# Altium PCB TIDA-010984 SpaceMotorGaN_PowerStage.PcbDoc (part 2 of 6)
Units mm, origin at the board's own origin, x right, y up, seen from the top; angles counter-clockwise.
Board outline 177.8 x 152.4 mm, 8 copper layers (Top Layer, DC LINK Layer 2, GND Layer 3, 3V3 Layer 4, Layer 5, Layer 6, GND Layer 7, Bottom Layer), stack 1.554 mm thick; 582 components, 280 nets, 1847 pads, 979 vias.
Unrouted connection lines stored in the file: 474.
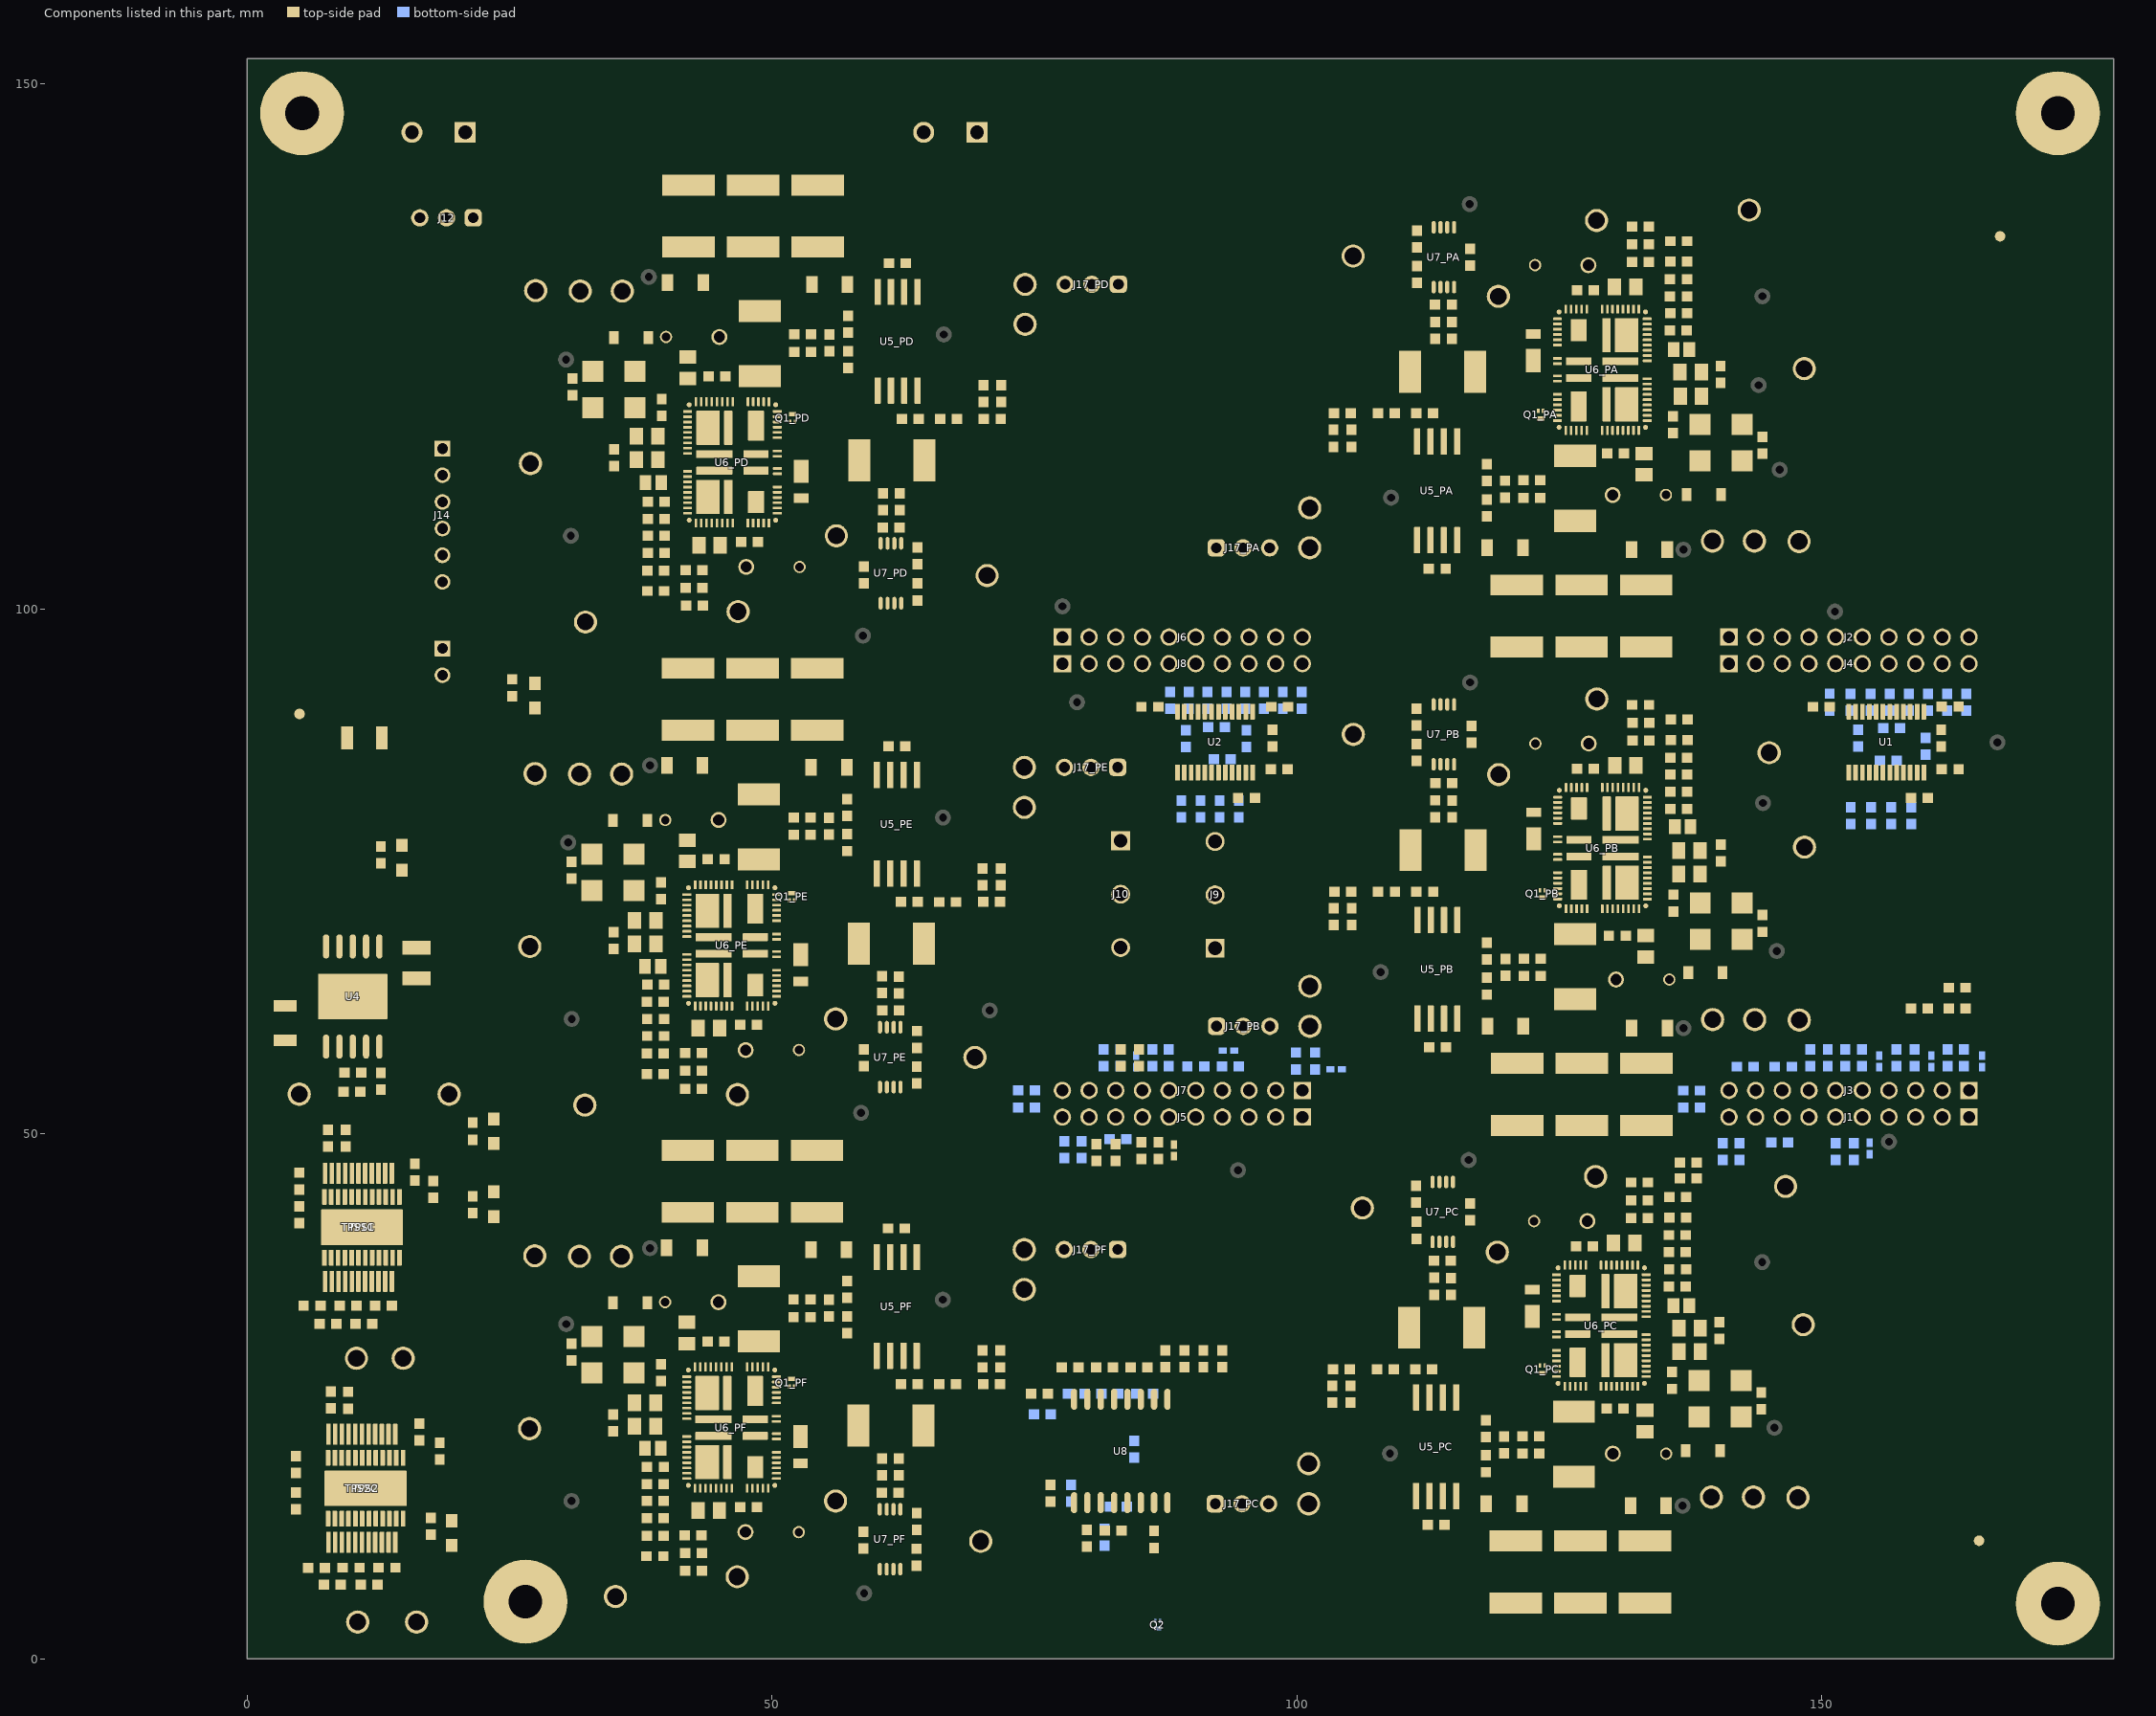
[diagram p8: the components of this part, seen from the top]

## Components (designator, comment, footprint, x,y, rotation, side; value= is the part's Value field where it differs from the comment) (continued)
R80_PC "RC0603FR-072R1L" 0603 144.25,24.547 r90 top locked value=2.10 (schematic designator R80)
R80_PD "RC0603FR-072R1L" 0603 31,121.141 r270 top locked value=2.10 (schematic designator R80)
R80_PE "RC0603FR-072R1L" 0603 30.932,75.129 r270 top locked value=2.10 (schematic designator R80)
R80_PF "RC0603FR-072R1L" 0603 30.918,29.205 r270 top value=2.10 (schematic designator R80)
R81_PA "RC0603FR-0710KL" 0603 132.758,133.046 r180 top value=10.0k (schematic designator R81)
R81_PB "RC0603FR-0710KL" 0603 132.78,87.477 r180 top value=10.0k (schematic designator R81)
R81_PC "RC0603FR-0710KL" 0603 132.66,41.99 r180 top locked value=10.0k (schematic designator R81)
R81_PD "RC0603FR-0710KL" 0603 42.59,103.698 r0 top locked value=10.0k (schematic designator R81)
R81_PE "RC0603FR-0710KL" 0603 42.522,57.686 r0 top locked value=10.0k (schematic designator R81)
R81_PF "RC0603FR-0710KL" 0603 42.508,11.762 r0 top value=10.0k (schematic designator R81)
R82_PA "CRCW060320R0FKEA" 0603 136.373,128.156 r0 top value=20.0 (schematic designator R82)
R82_PB "CRCW060320R0FKEA" 0603 136.395,82.587 r0 top value=20.0 (schematic designator R82)
R82_PC "CRCW060320R0FKEA" 0603 136.275,37.1 r0 top locked value=20.0 (schematic designator R82)
R82_PD "CRCW060320R0FKEA" 0603 38.975,108.588 r180 top locked value=20.0 (schematic designator R82)
R82_PE "CRCW060320R0FKEA" 0603 38.907,62.576 r180 top locked value=20.0 (schematic designator R82)
R82_PF "CRCW060320R0FKEA" 0603 38.893,16.652 r180 top value=20.0 (schematic designator R82)
R83_PA "CRCW060320R0FKEA" 0603 136.364,129.784 r0 top value=20.0 (schematic designator R83)
R83_PB "CRCW060320R0FKEA" 0603 136.386,84.215 r0 top value=20.0 (schematic designator R83)
R83_PC "CRCW060320R0FKEA" 0603 136.266,38.728 r0 top locked value=20.0 (schematic designator R83)
R83_PD "CRCW060320R0FKEA" 0603 38.984,106.96 r180 top locked value=20.0 (schematic designator R83)
R83_PE "CRCW060320R0FKEA" 0603 38.916,60.948 r180 top locked value=20.0 (schematic designator R83)
R83_PF "CRCW060320R0FKEA" 0603 38.902,15.024 r180 top value=20.0 (schematic designator R83)
R84_PA "RC0603JR-070RL" 0603 132.737,136.43 r0 top value=0 (schematic designator R84)
R84_PB "RC0603JR-070RL" 0603 132.759,90.861 r0 top value=0 (schematic designator R84)
R84_PC "RC0603JR-070RL" 0603 132.639,45.374 r0 top locked value=0 (schematic designator R84)
R84_PD "RC0603JR-070RL" 0603 42.611,100.314 r180 top locked value=0 (schematic designator R84)
R84_PE "RC0603JR-070RL" 0603 42.543,54.302 r180 top locked value=0 (schematic designator R84)
R84_PF "RC0603JR-070RL" 0603 42.529,8.378 r180 top value=0 (schematic designator R84)
R85_PA "CRE2512-FZ-R005E-3" CRE2512-R5_R9 113.912,122.598 r180 top locked value=0.005 (schematic designator R85)
R85_PB "CRE2512-FZ-R005E-3" CRE2512-R5_R9 113.934,77.029 r180 top value=0.005 (schematic designator R85)
R85_PC "CRE2512-FZ-R005E-3" CRE2512-R5_R9 113.814,31.542 r180 top locked value=0.005 (schematic designator R85)
R85_PD "CRE2512-FZ-R005E-3" CRE2512-R5_R9 61.436,114.146 r0 top locked value=0.005 (schematic designator R85)
R85_PE "CRE2512-FZ-R005E-3" CRE2512-R5_R9 61.368,68.134 r0 top locked value=0.005 (schematic designator R85)
R85_PF "CRE2512-FZ-R005E-3" CRE2512-R5_R9 61.354,22.21 r0 top value=0.005 (schematic designator R85)
R86_PA "RC0603FR-0757K6L" 0603 136.4,135.031 r0 top value=57.6k (schematic designator R86)
R86_PB "RC0603FR-0757K6L" 0603 136.423,89.462 r0 top value=57.6k (schematic designator R86)
R86_PC "RC0603FR-0757K6L" 0603 136.302,43.975 r0 top locked value=57.6k (schematic designator R86)
R86_PD "RC0603FR-0757K6L" 0603 38.948,101.713 r180 top locked value=57.6k (schematic designator R86)
R86_PE "RC0603FR-0757K6L" 0603 38.879,55.701 r180 top locked value=57.6k (schematic designator R86)
R86_PF "RC0603FR-0757K6L" 0603 38.865,9.777 r180 top value=57.6k (schematic designator R86)
R87_PA "RC0603JR-070RL" 0603 132.749,134.734 r0 top value=0 (schematic designator R87)
R87_PB "RC0603JR-070RL" 0603 132.771,89.165 r0 top value=0 (schematic designator R87)
R87_PC "RC0603JR-070RL" 0603 132.651,43.678 r0 top locked value=0 (schematic designator R87)
R87_PD "RC0603JR-070RL" 0603 42.599,102.01 r180 top locked value=0 (schematic designator R87)
R87_PE "RC0603JR-070RL" 0603 42.531,55.998 r180 top locked value=0 (schematic designator R87)
R87_PF "RC0603JR-070RL" 0603 42.517,10.074 r180 top value=0 (schematic designator R87)
R88_PA "RC0603FR-07100KL" 0603 104.348,118.644 r0 top locked value=100k (schematic designator R88)
R88_PB "RC0603FR-07100KL" 0603 104.37,73.075 r0 top locked value=100k (schematic designator R88)
R88_PC "RC0603FR-07100KL" 0603 104.25,27.589 r0 top locked value=100k (schematic designator R88)
R88_PD "RC0603FR-07100KL" 0603 71,118.1 r180 top locked value=100k (schematic designator R88)
R88_PE "RC0603FR-07100KL" 0603 70.932,72.088 r180 top locked value=100k (schematic designator R88)
R88_PF "RC0603FR-07100KL" 0603 70.918,26.163 r180 top value=100k (schematic designator R88)
R89_PA "RC0603JR-070RL" 0603 114.78,126.525 r90 top locked value=0 (schematic designator R89)
R89_PB "RC0603JR-070RL" 0603 114.802,80.956 r90 top value=0 (schematic designator R89)
R89_PC "RC0603JR-070RL" 0603 114.682,35.469 r90 top locked value=0 (schematic designator R89)
R89_PD "RC0603JR-070RL" 0603 60.568,110.219 r270 top locked value=0 (schematic designator R89)
R89_PE "RC0603JR-070RL" 0603 60.5,64.207 r270 top locked value=0 (schematic designator R89)
R89_PF "RC0603JR-070RL" 0603 60.486,18.282 r270 top value=0 (schematic designator R89)
R90_PA "RC0603JR-070RL" 0603 113.18,126.538 r90 top locked value=0 (schematic designator R90)
R90_PB "RC0603JR-070RL" 0603 113.202,80.969 r90 top value=0 (schematic designator R90)
R90_PC "RC0603JR-070RL" 0603 113.082,35.482 r90 top locked value=0 (schematic designator R90)
R90_PD "RC0603JR-070RL" 0603 62.168,110.206 r270 top locked value=0 (schematic designator R90)
R90_PE "RC0603JR-070RL" 0603 62.1,64.194 r270 top locked value=0 (schematic designator R90)
R90_PF "RC0603JR-070RL" 0603 62.086,18.269 r270 top value=0 (schematic designator R90)
R91_PA "RC0603FR-0735K7L" 0603 136.395,133.091 r0 top value=35.7k (schematic designator R91)
R91_PB "RC0603FR-0735K7L" 0603 136.417,87.522 r0 top value=35.7k (schematic designator R91)
R91_PC "RC0603FR-0735K7L" 0603 136.297,42.035 r0 top locked value=35.7k (schematic designator R91)
R91_PD "RC0603FR-0735K7L" 0603 38.953,103.653 r180 top locked value=35.7k (schematic designator R91)
R91_PE "RC0603FR-0735K7L" 0603 38.885,57.641 r180 top locked value=35.7k (schematic designator R91)
R91_PF "RC0603FR-0735K7L" 0603 38.871,11.717 r180 top value=35.7k (schematic designator R91)
R92_PA "RC0603FR-074K22L" 0603 105.207,116.25 r90 top locked value=4.22k (schematic designator R92)
R92_PB "RC0603FR-074K22L" 0603 105.229,70.681 r90 top locked value=4.22k (schematic designator R92)
R92_PC "RC0603FR-074K22L" 0603 105.109,25.194 r90 top locked value=4.22k (schematic designator R92)
R92_PD "RC0603FR-074K22L" 0603 70.141,120.494 r270 top locked value=4.22k (schematic designator R92)
R92_PE "RC0603FR-074K22L" 0603 70.073,74.482 r270 top locked value=4.22k (schematic designator R92)
R92_PF "RC0603FR-074K22L" 0603 70.059,28.558 r270 top value=4.22k (schematic designator R92)
R93_ "RC0603FR-0710KL" 0603 130.531,68.873 r0 top value=10.0k (schematic designator R93)
R93_ "RC0603FR-0710KL" 0603 44.684,30.221 r180 top value=10.0k (schematic designator R93)
R93_ "RC0603FR-0710KL" 0603 44.698,76.145 r180 top value=10.0k (schematic designator R93)
R93_ "RC0603FR-0710KL" 0603 44.766,122.157 r180 top value=10.0k (schematic designator R93)
R93_ "RC0603FR-0710KL" 0603 130.307,23.848 r0 top locked value=10.0k (schematic designator R93)
R93_ "RC0603FR-0710KL" 0603 130.358,114.806 r0 top value=10.0k (schematic designator R93)
R94_PA "RC0603JR-070RL" 0603 111.469,135.25 r270 top value=0 (schematic designator R94)
R94_PB "RC0603JR-070RL" 0603 111.403,89.695 r270 top value=0 (schematic designator R94)
R94_PC "RC0603JR-070RL" 0603 111.371,44.25 r270 top value=0 (schematic designator R94)
R94_PD "RC0603JR-070RL" 0603 63.879,101.619 r90 top value=0 (schematic designator R94)
R94_PE "RC0603JR-070RL" 0603 63.797,55.607 r90 top value=0 (schematic designator R94)
R94_PF "RC0603JR-070RL" 0603 63.783,9.682 r90 top value=0 (schematic designator R94)
R95_PA "RC0603FR-0710KL" 0603 127.487,130.35 r0 top value=10.0k (schematic designator R95)
R95_PB "RC0603FR-0710KL" 0603 127.509,84.781 r0 top value=10.0k (schematic designator R95)
R95_PC "RC0603FR-0710KL" 0603 127.389,39.294 r0 top locked value=10.0k (schematic designator R95)
R95_PD "RC0603FR-0710KL" 0603 47.861,106.394 r180 top locked value=10.0k (schematic designator R95)
R95_PE "RC0603FR-0710KL" 0603 47.793,60.382 r180 top locked value=10.0k (schematic designator R95)
R95_PF "RC0603FR-0710KL" 0603 47.779,14.458 r180 top value=10.0k (schematic designator R95)
R96 "RC0603FR-0710KL" 0603 87.471,28.581 r90 top value=10.0k
R97 "RC0603FR-0710KL" 0603 89.285,28.581 r90 top value=10.0k
R98 "RC0603FR-0710KL" 0603 92.913,28.581 r90 top value=10.0k
R99 "RC0603FR-0710KL" 0603 91.099,28.581 r90 top value=10.0k
R100 "RC0603JR-070RL" 0603 86.408,11.371 r270 top value=0
R101 "RC0603JR-070RL" 0603 84.957,27.75 r180 top value=0
R102 "CRCW060313K3FKEA" 0603 12.75,76.569 r90 top value=13.3k
R103 "RC0603JR-070RL" 0603 82.5,12.221 r180 top value=0
R104 "RC0603JR-070RL" 0603 81.707,27.75 r180 top value=0
R105 "RC0603JR-070RL" 0603 76.55,15.75 r270 top value=0
R106 "RC0603JR-070RL" 0603 75.5,25.25 r0 top value=0
R107 "RC0603JR-070RL" 0603 80,11.5 r270 top value=0
R108 "RC0603JR-070RL" 0603 78.412,27.75 r0 top value=0
R109 "RC0603FR-0720RL" 0603 74.25,54.142 r0 bottom value=20.0
R110 "CRCW060313K3FKEA" 0603 25.25,92.5 r90 top locked value=13.3k
R111 "RC0603FR-076K65L" 0603 21.5,43.25 r90 top value=6.65k
R112 "RC0603FR-074K22L" 0603 17.5,12.64 r90 top value=4.22k
R113 "RC0603FR-0720RL" 0603 82.95,49.5 r0 bottom value=20.0
R114 "RC0603FR-072K1L" 0603 21.5,50.25 r90 top value=2.10k
R115 "RC0603JR-070RL" 0603 137.307,45.75 r0 top value=0
R116 "RC0603JR-070RL" 0603 137.296,47.25 r0 top value=0
R117 "RC0603JR-070RL" 0603 80.907,48.22 r90 top value=0
R118 "RC0603JR-070RL" 0603 82.756,48.22 r90 top value=0
TP1 "5010" Keystone5010 14.875,28.624 r0 top locked
TP2 "5012" Keystone5012 10.423,28.624 r0 top locked
TP3 "5010" Keystone5010 16.153,3.5 r0 top locked
TP4 "5012" Keystone5012 10.549,3.5 r0 top locked
TP5 "5010" Keystone5010 4.973,53.784 r0 top locked
TP6_PA "5129" Keystone5129 101.228,105.821 r180 top locked (schematic designator TP6)
TP6_PB "5129" Keystone5129 101.25,60.252 r180 top locked (schematic designator TP6)
TP6_PC "5129" Keystone5129 101.13,14.766 r180 top locked (schematic designator TP6)
TP6_PD "5129" Keystone5129 74.12,130.923 r0 top locked (schematic designator TP6)
TP6_PE "5129" Keystone5129 74.052,84.911 r0 top locked (schematic designator TP6)
TP6_PF "5129" Keystone5129 74.038,38.986 r0 top (schematic designator TP6)
TP7_PA "5010" Keystone5010 148.348,122.887 r180 top locked (schematic designator TP7)
TP7_PB "5010" Keystone5010 148.37,77.318 r180 top (schematic designator TP7)
TP7_PC "5010" Keystone5010 148.25,31.831 r180 top locked (schematic designator TP7)
TP7_PD "5010" Keystone5010 27,113.857 r0 top locked (schematic designator TP7)
TP7_PE "5010" Keystone5010 26.932,67.845 r0 top locked (schematic designator TP7)
TP7_PF "5010" Keystone5010 26.918,21.921 r0 top (schematic designator TP7)
TP8_PA "5010" Keystone5010 143.598,106.46 r180 top locked (schematic designator TP8)
TP8_PB "5010" Keystone5010 143.62,60.891 r180 top (schematic designator TP8)
TP8_PC "5010" Keystone5010 143.5,15.404 r180 top locked (schematic designator TP8)
TP8_PD "5010" Keystone5010 31.75,130.284 r0 top locked (schematic designator TP8)
TP8_PE "5010" Keystone5010 31.682,84.272 r0 top locked (schematic designator TP8)
TP8_PF "5010" Keystone5010 31.668,38.348 r0 top (schematic designator TP8)
TP9_PA "5010" Keystone5010 128.565,136.994 r180 top locked (schematic designator TP9)
TP9_PB "5010" Keystone5010 128.587,91.425 r180 top (schematic designator TP9)
TP9_PC "5010" Keystone5010 128.467,45.938 r180 top locked (schematic designator TP9)
TP9_PD "5010" Keystone5010 46.783,99.75 r0 top locked (schematic designator TP9)
TP9_PE "5010" Keystone5010 46.715,53.738 r0 top locked (schematic designator TP9)
TP9_PF "5010" Keystone5010 46.701,7.814 r0 top (schematic designator TP9)
TP10 "5010" Keystone5010 19.25,53.784 r0 top locked
TP10_PA "5013" Keystone5013 119.206,129.784 r270 top locked (schematic designator TP10)
TP10_PB "5013" Keystone5013 119.229,84.215 r270 top (schematic designator TP10)
TP10_PC "5013" Keystone5013 119.109,38.728 r270 top locked (schematic designator TP10)
TP10_PD "5013" Keystone5013 56.141,106.96 r90 top locked (schematic designator TP10)
TP10_PE "5013" Keystone5013 56.073,60.948 r90 top locked (schematic designator TP10)
TP10_PF "5013" Keystone5013 56.059,15.024 r90 top (schematic designator TP10)
TP11_PA "5010" Keystone5010 139.598,106.46 r180 top locked (schematic designator TP11)
TP11_PB "5010" Keystone5010 139.62,60.891 r180 top (schematic designator TP11)
TP11_PC "5010" Keystone5010 139.5,15.404 r180 top locked (schematic designator TP11)
TP11_PD "5010" Keystone5010 35.75,130.284 r0 top locked (schematic designator TP11)
TP11_PE "5010" Keystone5010 35.682,84.272 r0 top locked (schematic designator TP11)
TP11_PF "5010" Keystone5010 35.668,38.348 r0 top (schematic designator TP11)
TP12_PA "5129" Keystone5129 101.228,109.631 r270 top locked (schematic designator TP12)
TP12_PB "5129" Keystone5129 101.25,64.062 r270 top locked (schematic designator TP12)
TP12_PC "5129" Keystone5129 101.13,18.576 r270 top locked (schematic designator TP12)
TP12_PD "5129" Keystone5129 74.12,127.113 r90 top locked (schematic designator TP12)
TP12_PE "5129" Keystone5129 74.052,81.101 r90 top locked (schematic designator TP12)
TP12_PF "5129" Keystone5129 74.038,35.176 r90 top (schematic designator TP12)
TP13_PA "HS_Gate" TESTPOINT_PIGTAIL 130.083,110.855 r90 top (schematic designator TP13)
TP13_PB "HS_Gate" TESTPOINT_PIGTAIL 130.406,64.7 r90 top (schematic designator TP13)
TP13_PC "HS_Gate" TESTPOINT_PIGTAIL 130.113,19.538 r90 top (schematic designator TP13)
TP13_PD "HS_Gate" TESTPOINT_PIGTAIL 44.992,125.907 r270 top (schematic designator TP13)
TP13_PE "HS_Gate" TESTPOINT_PIGTAIL 44.924,79.895 r270 top (schematic designator TP13)
TP13_PF "HS_Gate" TESTPOINT_PIGTAIL 44.91,33.971 r270 top (schematic designator TP13)
TP14_PA "LS_Gate" TESTPOINT_PIGTAIL 127.786,132.744 r270 top (schematic designator TP14)
TP14_PB "LS_Gate" TESTPOINT_PIGTAIL 127.808,87.175 r270 top (schematic designator TP14)
TP14_PC "LS_Gate" TESTPOINT_PIGTAIL 127.688,41.688 r270 top locked (schematic designator TP14)
TP14_PD "LS_Gate" TESTPOINT_PIGTAIL 47.562,104 r90 top locked (schematic designator TP14)
TP14_PE "LS_Gate" TESTPOINT_PIGTAIL 47.494,57.988 r90 top locked (schematic designator TP14)
TP14_PF "LS_Gate" TESTPOINT_PIGTAIL 47.48,12.064 r90 top (schematic designator TP14)
TP16_PA "5011" Keystone5011 147.848,106.413 r270 top locked (schematic designator TP16)
TP16_PB "5011" Keystone5011 147.87,60.844 r270 top (schematic designator TP16)
TP16_PC "5011" Keystone5011 147.75,15.357 r270 top locked (schematic designator TP16)
TP16_PD "5011" Keystone5011 27.5,130.331 r90 top locked (schematic designator TP16)
TP16_PE "5011" Keystone5011 27.432,84.319 r90 top locked (schematic designator TP16)
TP16_PF "5011" Keystone5011 27.418,38.395 r90 top (schematic designator TP16)
TP17_PA "5011" Keystone5011 143.098,137.994 r270 top locked (schematic designator TP17)
TP17_PB "5011" Keystone5011 145,86.303 r270 top (schematic designator TP17)
TP17_PC "5011" Keystone5011 146.57,45 r270 top locked (schematic designator TP17)
TP17_PD "5011" Keystone5011 32.25,98.75 r90 top locked (schematic designator TP17)
TP17_PE "5011" Keystone5011 32.182,52.738 r90 top (schematic designator TP17)
TP17_PF "5011" Keystone5011 35.091,5.931 r90 top (schematic designator TP17)
TP18_PA "5011" Keystone5011 105.366,133.618 r270 top locked (schematic designator TP18)
TP18_PB "5011" Keystone5011 105.389,88.049 r270 top locked (schematic designator TP18)
TP18_PC "5011" Keystone5011 106.25,42.949 r270 top (schematic designator TP18)
TP18_PD "5011" Keystone5011 70.5,103.173 r90 top (schematic designator TP18)
TP18_PE "5011" Keystone5011 69.343,57.276 r90 top (schematic designator TP18)
TP18_PF "5011" Keystone5011 69.9,11.189 r90 top (schematic designator TP18)
TPS1 "TPS7H1121MPWPTSEP" PWP0024R-MFG 10.943,41.098 r270 top
TPS1C "TPS7H1121HFT/EM" HFT0022A-C01-MFG 10.618,41.098 r270 top
TPS2 "TPS7H1121MPWPTSEP" PWP0024R-MFG 11.292,16.24 r270 top locked
TPS2C "TPS7H1121HFT/EM" HFT0022A-C01-MFG 10.943,16.24 r270 top locked
U1 "SN54SLC8T245PWTSEP" PW0024A-MFG 156.166,87.316 r270 top locked
U2 "SN54SLC8T245PWTSEP" PW0024A-MFG 92.216,87.316 r270 top locked
U4 "TPS7A4501HKU/EM" HKU0010A-IPC_B 10.069,63.081 r270 top
U5_PA "INA901HKX/EM" HKX0008A_Custom_A 113.374,111.246 r270 top locked (schematic designator U5)
U5_PB "INA901HKX/EM" HKX0008A_Custom_A 113.396,65.677 r270 top (schematic designator U5)
U5_PC "INA901HKX/EM" HKX0008A_Custom_A 113.276,20.19 r270 top locked (schematic designator U5)
U5_PD "INA901HKX/EM" HKX0008A_Custom_A 61.974,125.498 r90 top locked (schematic designator U5)
U5_PE "INA901HKX/EM" HKX0008A_Custom_A 61.906,79.486 r90 top locked (schematic designator U5)
U5_PF "INA901HKX/EM" HKX0008A_Custom_A 61.892,33.562 r90 top (schematic designator U5)
U6_PA "TPS7H6101MNPRTSHP" NPR0064A-MFG 129.107,122.785 r180 top (schematic designator U6)
U6_PB "TPS7H6101MNPRTSHP" NPR0064A-MFG 129.129,77.216 r180 top (schematic designator U6)
U6_PC "TPS7H6101MNPRTSHP" NPR0064A-MFG 129.009,31.729 r180 top locked (schematic designator U6)
U6_PD "TPS7H6101MNPRTSHP" NPR0064A-MFG 46.241,113.959 r0 top locked (schematic designator U6)
U6_PE "TPS7H6101MNPRTSHP" NPR0064A-MFG 46.173,67.947 r0 top locked (schematic designator U6)
U6_PF "TPS7H6101MNPRTSHP" NPR0064A-MFG 46.159,22.023 r0 top (schematic designator U6)
U7_PA "INA240A1PWR" PW0008A_L 114.009,133.5 r90 top (schematic designator U7)
U7_PB "INA240A1PWR" PW0008A_L 114.009,88.049 r90 top (schematic designator U7)
U7_PC "INA240A1PWR" PW0008A_L 113.911,42.563 r90 top (schematic designator U7)
U7_PD "INA240A1PWR" PW0008A_L 61.339,103.397 r270 top (schematic designator U7)
U7_PE "INA240A1PWR" PW0008A_L 61.271,57.31 r270 top (schematic designator U7)
U7_PF "INA240A1PWR" PW0008A_L 61.257,11.386 r270 top (schematic designator U7)
U8 "5962R2021401VXC" HKT0016A-IPC_C 83.233,19.798 r90 top
ZZ1 "This Assembly Note is for PCB labels only" AssemblyNoteLabel 3.515,163.673 r0 top
ZZ2 "These assemblies are ESD sensitive, ESD precautions shall be observed." AssemblyNote 4.719,157.75 r0 top
ZZ3 "These assemblies must be clean and free from flux and all contaminants. Use of no clean flux is not acceptable." AssemblyNote 4.519,154.75 r0 top
ZZ4 "These assemblies must comply with workmanship standards IPC-A-610 Class 2, unless otherwise specified." AssemblyNote 3.5,161.5 r0 top

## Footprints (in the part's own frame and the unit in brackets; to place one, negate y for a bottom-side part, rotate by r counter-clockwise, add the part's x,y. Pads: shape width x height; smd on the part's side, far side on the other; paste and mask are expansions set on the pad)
0603 [mm] "0603 from SM-752 data"
  rect 1x0.95 smd: 1(-0.8,0) 2(0.8,0)
  silkscreen extent -1.52,-0.69 1.52,0.69, body extent -0.87,-0.47 0.87,0.47, height 1
0805_HV [mil] "0805 with 30mil clearance between pads"
  rect 50x63 smd: 1(-40,0) 2(40,0)
  silkscreen extent -74,-40 74,40, body extent -43,-29 43,29, height 57
0805L [mm] "0805 from SM-752 data"
  rect 1.1x1.4 smd: 1(-0.75,0) 2(0.75,0)
  body extent -1.1,-0.72 1.1,0.72, height 1.45
1206_180 [mm] "1206_180"
  rect 1.1x1.6 smd: 1(-1.7,0) 2(1.7,0)
  silkscreen extent -0.9,-1 0.9,1, body extent -1.75,-0.95 1.75,0.95, height 1.8
1210_150 [mm] "1210"
  rect 1.3x2.7 smd: 1(-1.45,0) 2(1.45,0)
  silkscreen extent -2.32,-1.57 2.32,1.57, body extent -1.7,-1.35 1.7,1.35, height 1.5
1210_280 [mm] "SMD, 2-Leads, Body 3.6x2.8mm, Height 2.8mm"
  rect 1.1x2.2 smd: 1(-1.65,0) 2(1.65,0)
  silkscreen extent -0.84,-1.4 0.84,1.4, body extent -1.8,-1.4 1.8,1.4, height 2.8
APT2012_Green [mm] "SMD, 2-Leads, Body 2x1.25mm"
  rect 1.25x1.1 smd: 1(-1.175,0) 2(1.175,0)
  silkscreen extent -1.5,-1 2.4,1, body extent -1,-0.62 1,0.63, height 0.76
AssemblyNote [mm] "Assembly Note"
AssemblyNoteLabel [mm] "Assembly Note for PCB Labels"
CE_Mark_5mm [mm] "Minimum text height for CE Mark"
  silkscreen extent -3.5,-2.5 3.5,2.5
CKG57N [mm] "Chip Capacitor, Body 6.0x5.0x5.0mm,"
  rect 2x5 smd: 1(-2.95,0) 2(2.95,0)
  silkscreen extent -3.2,-2.8 3.2,2.8, body extent -3.3,-2.75 3.3,2.75, height 5.5
CONN_PEC02SAAN [mm] "SULLINS"
  rrect7% 1.5x1.5 hole 1.016: 1(-1.27,0)
  round 1.5 hole 1.016: 2(1.27,0)
  silkscreen extent -2.54,-1.52 2.54,1.27, body extent -2.54,-1.27 2.54,1.27, height 8.38
CONN_SSW-110-23-F-S [mm] "SAMTEC"
  rect 1.65x1.65 hole 1.15: 1(11.43,0)
  round 1.65 hole 1.15: 2(8.89,0) 3(6.35,0) 4(3.81,0) 5(1.27,0) 6(-1.27,0) 7(-3.81,0) 8(-6.35,0) 9(-8.89,0) 10(-11.43,0)
  silkscreen extent -13.08,-1.27 13.08,1.27, body extent -13,-1.27 13,1.27, height 8.59
CRE2512-R5_R9 [mm] "SMD, 2-Leads, Body 6.45x3.35mm, Pitch 6.2mm"
  rect 2.1x4 smd: 1(-3.1,0) 2(3.1,0)
  silkscreen extent -1.6,-1.78 1.6,1.78, body extent -3.32,-1.77 3.32,1.77, height 0.9
DIODES_X1-DFN1006-3 [mm] "Diodes Recommended"
  rect 0.4x0.25 smd: 1(-0.35,0.225) 2(-0.35,-0.225)
  rect 0.4x0.7 smd: 3(0.35,0)
  silkscreen extent -0.87,-0.38 -0.69,0.38, body extent -0.54,-0.34 0.54,0.34, height 0.53
FCC_disclaimer [mm]
Fiducial10-20 [mm]
  round 1 smd mask+0.5: 1(0,0)
  Top Layer keep-out circle w1.178: c0,0 r0.5
HFT0022A-C01-MFG [mm]
  rrect23% 2x0.435 smd paste+0 mask+0: 1(-5.145,3.175) 2(-5.145,2.54) 3(-5.145,1.905) 4(-5.145,1.27) 5(-5.145,0.635) 6(-5.145,0) 7(-5.145,-0.635) 8(-5.145,-1.27) 9(-5.145,-1.905) 10(-5.145,-2.54) 11(-5.145,-3.175) 12(5.145,-3.175) 13(5.145,-2.54) 14(5.145,-1.905) 15(5.145,-1.27) 16(5.145,-0.635) 17(5.145,0) 18(5.145,0.635) 19(5.145,1.27) 20(5.145,1.905) 21(5.145,2.54) 22(5.145,3.175)
  silkscreen extent -6.83,-3.97 3.23,3.3, body extent -6.24,-4.07 6.24,4.07, height 0.25
HKT0016A-IPC_C [mm]
  rrect100% 2x0.6 smd paste+0 mask+0: 1(-4.925,4.445) 2(-4.925,3.175) 3(-4.925,1.905) 4(-4.925,0.635) 5(-4.925,-0.635) 6(-4.925,-1.905) 7(-4.925,-3.175) 8(-4.925,-4.445) 9(4.925,-4.445) 10(4.925,-3.175) 11(4.925,-1.905) 12(4.925,-0.635) 13(4.925,0.635) 14(4.925,1.905) 15(4.925,3.175) 16(4.925,4.445)
  silkscreen extent -6.62,-5.21 3.72,5.21, body extent -6.02,-5.35 6.02,5.35, height 0.25
HKU0010A-IPC_B [mm]
  rrect100% 2.3x0.6 smd paste+0 mask+0: 1(-4.775,2.54) 2(-4.775,1.27) 3(-4.775,0) 4(-4.775,-1.27) 5(-4.775,-2.54) 6(4.775,-2.54) 7(4.775,-1.27) 8(4.775,0) 9(4.775,1.27) 10(4.775,2.54)
  rrect2% 4.3x6.62 smd paste+0 mask+0: 11(0,0)
  silkscreen extent -6.62,-3.63 3.53,3.63, body extent -6.17,-3.9 6.17,3.9, height 0.25
HKX0008A_Custom_A [mm] "CFP, 8-Leads, Body 6.475x6.485mm, Pitch 1.27mm"
  rrect17% 2.5x0.6 smd: 1(-4.7,1.905) 2(-4.7,0.635) 3(-4.7,-0.635) 4(-4.7,-1.905) 5(4.7,-1.905) 6(4.7,-0.635) 7(4.7,0.635) 8(4.7,1.905)
  silkscreen extent -5.5,-3.36 3.37,3.36, body extent -3.25,-3.24 3.25,3.24, height 2.51
IEC_HotSurface_Small [mm]
  silkscreen extent -2.72,-2.36 2.72,2.35
Keystone5010 [mil] "Keystone Multipurpose loops"
  round 87 hole 63: 1(0,0)
  silkscreen extent -70,-70 70,70, body extent -63,-63 63,62, height 319
Keystone5011 [mil] "Keystone Multipurpose loops"
  round 87 hole 63: 1(0,0)
  silkscreen extent -70,-70 70,70, body extent -63,-63 63,62, height 319
Keystone5012 [mil] "Keystone Multipurpose loops"
  round 87 hole 63: 1(0,0)
  silkscreen extent -70,-70 70,70, body extent -63,-63 63,62, height 319
Keystone5013 [mil] "Keystone Multipurpose loops"
  round 87 hole 63: 1(0,0)
  silkscreen extent -70,-70 70,70, body extent -63,-63 63,62, height 319
Keystone5129 [mil] "Keystone Multipurpose loops"
  round 87 hole 63: 1(0,0)
  silkscreen extent -70,-70 70,70, body extent -63,-63 63,62, height 319
Label_650x200 [mil] "Thermal Transfer Label"
  round 1 on Mech13: 0(0,0)
  silkscreen extent -325,-100 325,100, body extent -325,-100 325,100, height 1
NPR0064A-MFG [mm]
  round 0.469 smd paste+0 mask+0: 1(-4.116,5.49) 51(4.116,5.49)
  rrect40% 0.85x0.25 smd paste+0 mask+0: 2(-4.275,4.85) 3(-4.275,4.35) 4(-4.275,3.85) 5(-4.275,3.35) 6(-4.275,2.85) 7(-4.275,2.35) 8(-4.275,1.85) 9(-4.275,1.35) 10(-4.275,0.85) 11(-4.275,-0.85) 12(-4.275,-1.35) 13(-4.275,-1.85) 14(-4.275,-2.35) 15(-4.275,-2.85) 16(-4.275,-3.35) 17(-4.275,-3.85) 18(-4.275,-4.35) 19(-4.275,-4.85) 35(4.275,-4.85) 36(4.275,-4.35) 37(4.275,-3.85) 38(4.275,-3.35) 39(4.275,-2.85) 40(4.275,-2.35) 41(4.275,-1.083) 42(4.275,-0.583) 43(4.275,0.583) 44(4.275,1.083) 45(4.275,2.35) 46(4.275,2.85) 47(4.275,3.35) 48(4.275,3.85) 49(4.275,4.35) 50(4.275,4.85)
  round 0.466 smd paste+0 mask+0: 20(-4.116,-5.51) 34(4.116,-5.51)
  rrect40% 0.25x0.85 smd paste+0 mask+0: 21(-3.476,-5.775) 22(-2.976,-5.775) 23(-2.476,-5.775) 24(-1.976,-5.775) 25(-1.476,-5.775) 26(-0.976,-5.775) 27(-0.476,-5.775) 28(0.024,-5.775) 29(1.476,-5.775) 30(1.976,-5.775) 31(2.476,-5.775) 32(2.976,-5.775) 33(3.476,-5.775) 52(3.476,5.775) 53(2.976,5.775) 54(2.476,5.775) 55(1.976,5.775) 56(1.476,5.775) 57(0.024,5.775) 58(-0.476,5.775) 59(-0.976,5.775) 60(-1.476,5.775) 61(-1.976,5.775) 62(-2.476,5.775) 63(-2.976,5.775) 64(-3.476,5.775)
  rrect4% 2.25x3.25 smd paste-1000 mask+0: 65(-2.325,3.293) 68(-2.325,-3.293)
  rrect13% 3.45x0.75 smd paste-1000 mask+0: 66(-1.725,0.793) 67(-1.725,-0.793)
  rrect13% 0.8x3.25 smd paste-1000 mask+0: 69(-0.4,-3.293) 74(-0.4,3.293)
  rrect7% 1.532x2.116 smd paste-1000 mask+0: 70(2.25,-3.779)
  rrect13% 2.4x0.75 smd paste-1000 mask+0: 71(2.25,-0.793) 72(2.25,0.793)
  rrect7% 1.532x2.85 smd paste-1000 mask+0: 73(2.25,3.493)
  Top Layer region: 4.101,-6.15 4.097,-6.169 4.086,-6.185 4.07,-6.196 4.051,-6.2 4.051,-6.2 3.901,-6.2 3.882,-6.196 3.866,-6.185 3.855,-6.169 3.851,-6.15 3.851,-6.15 3.851,-5.275 3.855,-5.256 3.866,-5.24 3.882,-5.229 3.901,-5.225 3.901,-5.225 4.65,-5.225 4.675,-5.232 4.693,-5.25 4.7,-5.275 4.7,-5.275 4.7,-5.425 4.696,-5.444 4.685,-5.46 4.669,-5.471 4.65,-5.475 4.65,-5.475 4.425,-5.475 4.4,-5.482 4.382,-5.5 4.375,-5.525 4.375,-5.525 4.375,-5.848 4.371,-5.867 4.36,-5.883 4.344,-5.894 4.325,-5.898 4.325,-5.898 4.151,-5.898 4.126,-5.905 4.108,-5.923 4.101,-5.948 4.101,-5.948
  Top Layer region: -4.101,6.15 -4.094,6.175 -4.076,6.193 -4.051,6.2 -4.051,6.2 -3.901,6.2 -3.882,6.196 -3.866,6.185 -3.855,6.169 -3.851,6.15 -3.851,6.15 -3.851,5.275 -3.855,5.256 -3.866,5.24 -3.882,5.229 -3.901,5.225 -3.901,5.225 -4.65,5.225 -4.675,5.232 -4.693,5.25 -4.7,5.275 -4.7,5.275 -4.7,5.425 -4.693,5.45 -4.675,5.468 -4.65,5.475 -4.65,5.475 -4.425,5.475 -4.406,5.479 -4.39,5.49 -4.379,5.506 -4.375,5.525 -4.375,5.525 -4.375,5.848 -4.368,5.873 -4.35,5.891 -4.325,5.898 -4.325,5.898 -4.151,5.898 -4.132,5.902 -4.116,5.913 -4.105,5.929 -4.101,5.948 -4.101,5.948
  Top Layer region: -4.101,-6.15 -4.097,-6.169 -4.086,-6.185 -4.07,-6.196 -4.051,-6.2 -4.051,-6.2 -3.901,-6.2 -3.882,-6.196 -3.866,-6.185 -3.855,-6.169 -3.851,-6.15 -3.851,-6.15 -3.851,-5.275 -3.855,-5.256 -3.866,-5.24 -3.882,-5.229 -3.901,-5.225 -3.901,-5.225 -4.65,-5.225 -4.675,-5.232 -4.693,-5.25 -4.7,-5.275 -4.7,-5.275 -4.7,-5.425 -4.696,-5.444 -4.685,-5.46 -4.669,-5.471 -4.65,-5.475 -4.65,-5.475 -4.425,-5.475 -4.4,-5.482 -4.382,-5.5 -4.375,-5.525 -4.375,-5.525 -4.375,-5.848 -4.371,-5.867 -4.36,-5.883 -4.344,-5.894 -4.325,-5.898 -4.325,-5.898 -4.151,-5.898 -4.132,-5.902 -4.116,-5.913 -4.105,-5.929 -4.101,-5.948 -4.101,-5.948
  Top Layer region: 4.101,6.15 4.097,6.169 4.086,6.185 4.07,6.196 4.051,6.2 4.051,6.2 3.901,6.2 3.882,6.196 3.866,6.185 3.855,6.169 3.851,6.15 3.851,6.15 3.851,5.275 3.855,5.256 3.866,5.24 3.882,5.229 3.901,5.225 3.901,5.225 4.65,5.225 4.675,5.232 4.693,5.25 4.7,5.275 4.7,5.275 4.7,5.425 4.696,5.444 4.685,5.46 4.669,5.471 4.65,5.475 4.65,5.475 4.425,5.475 4.4,5.482 4.382,5.5 4.375,5.525 4.375,5.525 4.375,5.848 4.371,5.867 4.36,5.883 4.344,5.894 4.325,5.898 4.325,5.898 4.151,5.898 4.126,5.905 4.108,5.923 4.101,5.948 4.101,5.948
  silkscreen extent -5.38,-6.22 4.72,6.22, body extent -5.2,-6.7 5.2,6.7, height 0.25
"NY PMS 440 0025 PH" [mm] "4-40 nylon screw and mounting hole"
  round 8 hole 3.2: 1(0,0)
  body extent -3.3,-3.3 3.3,3.3, height 2.69
On-Shore_OSTTC022162 [mm] "THD, 2-Leads, Body 10.16x7.6mm, Pitch 5.08mm"
  rect 2x2 hole 1.3: 1(-2.54,-0.4)
  round 2 hole 1.3: 2(2.54,-0.4)
  silkscreen extent -5.86,-3.8 5.6,3.8, body extent -5.58,-3.8 5.6,3.8, height 10.31
On-Shore_OSTTC032162 [mm] "Terminal Block, 3x1, 5.08 mm, TH"
  rect 1.8x1.8 hole 1.3: 1(-5.08,0)
  round 1.8 hole 1.3: 2(0,0) 3(5.08,0)
  silkscreen extent -7.62,-3.8 7.62,4.2, body extent -7.62,-3.3 7.62,4.2, height 10
Pb-Free_Overlay_Small [mm]
  silkscreen extent -1.16,-1.17 1.17,1.17
PowerDI123 [mm] "Diodes Inc recommended land pattern, document number DS30628 Rev. 6-2"
  rect 2.2x1.4 smd: 1(-1.275,0)
  rect 0.9x1.4 smd: 2(1.275,0)
  silkscreen extent -3.1,-1.09 1.76,1.09, body extent -2.38,-0.97 1.52,0.96, height 1
PW0008A_L [mm] "TSOP, 8-Leads, Body 3x4.4mm, Pitch 0.65mm, IPC High Density"
  oval 1.2x0.4 smd: 1(-2.85,0.975) 2(-2.85,0.325) 3(-2.85,-0.325) 4(-2.85,-0.975) 5(2.85,-0.975) 6(2.85,-0.325) 7(2.85,0.325) 8(2.85,0.975)
  silkscreen extent -3.2,-1.55 1.85,1.55, body extent -3.21,-1.5 3.21,1.5, height 1.2
PW0024A-MFG [mm]
  rrect22% 1.5x0.45 smd paste+0 mask+0: 1(-2.9,3.575) 2(-2.9,2.925) 3(-2.9,2.275) 4(-2.9,1.625) 5(-2.9,0.975) 6(-2.9,0.325) 7(-2.9,-0.325) 8(-2.9,-0.975) 9(-2.9,-1.625) 10(-2.9,-2.275) 11(-2.9,-2.925) 12(-2.9,-3.575) 13(2.9,-3.575) 14(2.9,-2.925) 15(2.9,-2.275) 16(2.9,-1.625) 17(2.9,-0.975) 18(2.9,-0.325) 19(2.9,0.325) 20(2.9,0.975) 21(2.9,1.625) 22(2.9,2.275) 23(2.9,2.925) 24(2.9,3.575)
  silkscreen extent -4.32,-3.95 1.78,3.95, body extent -3.2,-3.9 3.2,3.9, height 1.2
PWP0024R-MFG [mm]
  rrect22% 1.5x0.45 smd paste+0 mask+0: 1(-2.9,3.575) 2(-2.9,2.925) 3(-2.9,2.275) 4(-2.9,1.625) 5(-2.9,0.975) 6(-2.9,0.325) 7(-2.9,-0.325) 8(-2.9,-0.975) 9(-2.9,-1.625) 10(-2.9,-2.275) 11(-2.9,-2.925) 12(-2.9,-3.575) 13(2.9,-3.575) 14(2.9,-2.925) 15(2.9,-2.275) 16(2.9,-1.625) 17(2.9,-0.975) 18(2.9,-0.325) 19(2.9,0.325) 20(2.9,0.975) 21(2.9,1.625) 22(2.9,2.275) 23(2.9,2.925) 24(2.9,3.575)
  rrect3% 3.4x7.8 smd paste-1000 mask-1000: 25(0,0)
  silkscreen extent -4.32,-4.3 2.25,4.3, body extent -3.75,-4.2 3.75,4.2, height 0.25
SMA [mm] "Molded Diode, 2-Leads, Body 4.3x2.6mm, IPC Medium Density, based on OnSemi component dimensions and land pattern"
  rect 2x2 smd: 1(-2,0) 2(2,0)
  silkscreen extent -3.66,-1.57 2.79,1.58, body extent -2.6,-1.3 2.6,1.3, height 2.42
SOD-123 [mm] "On Semi recommended land pattern"
  rect 0.915x1.22 smd: 1(-1.637,0) 2(1.637,0)
  silkscreen extent -2.74,-1.17 2.03,1.17, body extent -1.93,-0.9 1.93,0.9, height 1.35
SOD-523 [mm] "NXP Semiconductor recommended land pattern, nominal STEP model"
  rect 0.8x0.6 smd paste-0.05: 1(-0.55,0) 2(0.55,0)
  silkscreen extent -1.65,-0.66 1.2,0.66, body extent -0.8,-0.4 0.8,0.4, height 0.72
Sullins_PEC06SAAN [mm] "TH, 6-Leads, Body 608x100mil, Pitch 100mil"
  rect 1.5x1.5 hole 1.016: 1(-6.35,0)
  round 1.5 hole 1.016: 2(-3.81,0) 3(-1.27,0) 4(1.27,0) 5(3.81,0) 6(6.35,0)
  silkscreen extent -8.64,-1.27 7.72,1.27, body extent -7.72,-1.27 7.72,1.27, height 8.59
TESTPOINT_PIGTAIL [mil] "Pigtail"
  round 60 hole 42: 1(0,0)
  round 46 hole 32: 2(0,-200)
  silkscreen extent -50,-233 50,50
TI_Stacked_Overlay_Small [mm]
  silkscreen extent -10.63,-2.49 10.63,2.49
TSW-103-07-G-S [mm] "Samtec 100mil, 1x3, 230 mil above insulator"
  rrect50% 1.65x1.65 hole 1.016: 1(-2.54,0)
  round 1.65 hole 1.016: 2(0,0) 3(2.54,0)
  body extent -3.81,-1.27 3.81,1.27, height 8.38
WEEE_Minimum [mm] "WEEElie bin"
  silkscreen extent -2.42,-4.38 2.52,2.65

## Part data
5 LOGO4: library part CMP-0074837-2, "IEC 61010-1 Hot Surface Warning", Manufacturer="Texas Instruments"
C1 C2 C11 C12 C31_PA C31_PB C31_PC C31_PD C31_PE C31_PF C50_PA C50_PB C50_PC C50_PD C50_PE C50_PF C56_PA C56_PB C56_PC C56_PD C56_PE C56_PF C57: library part CMP-0007378-5, "CAP, CERM, 0.1 uF, 16 V, +/- 10%, X7R, 0603", Cap_Case=0603, Manufacturer=MuRata, Supplier Part Number 1=490-1532-1-ND, TempCo=X7R, Tolerance_%=10%, Value1=Unknown, Value2=16V, ValueDisplayed=0.1uF
C3 C4 C5 C6 C7 C8 C9 C10 C13 C14 C15 C16 C17 C18 C28 C61: "CAP, CERM, 2200 pF, 16 V, +/- 10%, X7R, 0603", Cap_Case=0603, Manufacturer="Wurth Elektronik", PartNumber=885012206036, Supplier Part Number 1=710-885012206036, TempCo=X7R, Tolerance_%=10%, Value1=Unknown, Value2=16V, ValueDisplayed=2200pF
C19 C20 C25 C53_PA C53_PB C53_PC C53_PD C53_PE C53_PF: library part CMP-0007392-5, "CAP, CERM, 0.033 uF, 16 V, +/- 10%, X7R, 0603", Cap_Case=0603, Manufacturer=MuRata, Supplier Part Number 1=490-1528-1-ND, TempCo=X7R, Tolerance_%=10%, Value1=Unknown, Value2=16V, ValueDisplayed=0.033uF
C21 C26: library part CMP-0007490-4, "CAP, CERM, 1000 pF, 250 V, +/- 10%, X7R, 0603", Cap_Case=0603, Manufacturer=MuRata, Supplier Part Number 1=490-3526-1-ND, TempCo=X7R, Tolerance_%=10%, Value1=Unknown, Value2=250V, ValueDisplayed=1000pF
C22 C27: library part CMP-0007424-4, "CAP, CERM, 0.47 uF, 25 V, +/- 10%, X7R, 0603", Cap_Case=0603, Manufacturer=MuRata, Supplier Part Number 1=490-3291-1-ND, TempCo=X7R, Tolerance_%=10%, Value1=Unknown, Value2=25V, ValueDisplayed=0.47uF
C23: library part CMP-0009061-1, "CAP, CERM, 1 uF, 25 V, +/- 10%, X7R, 1210", Cap_Case=1210, Manufacturer=AVX, Supplier Part Number 1=478-3816-1-ND, TempCo=X7R, Tolerance_%=10%, Value1=Unknown, Value2=25V, ValueDisplayed=1uF
C24 C30: library part CMP-0009078-1, "CAP, CERM, 10 uF, 25 V, +/- 10%, X7R, 1210", Cap_Case=1210, Manufacturer=Kemet, Supplier Part Number 1=399-8224-1-ND, TempCo=X7R, Tolerance_%=10%, Value1=Unknown, Value2=25V, ValueDisplayed=10uF
C29: library part CMP-0007495-4, "CAP, CERM, 470 pF, 250 V, +/- 10%, X7R, 0603", Cap_Case=0603, Manufacturer=MuRata, Supplier Part Number 1=490-3523-1-ND, TempCo=X7R, Tolerance_%=10%, Value1=Unknown, Value2=250V, ValueDisplayed=470pF
C32 C33 C34 C45 C58 C59 C60: library part CMP-0006826-4, "CAP, CERM, 1000 pF, 16 V, +/- 10%, X7R, 0603", Cap_Case=0603, Manufacturer="Wurth Elektronik", Supplier Part Number 1=710-885012206034, TempCo=X7R, Tolerance_%=10%, Value1=Unknown, Value2=16V, ValueDisplayed=1000pF
C35_PA C35_PB C35_PC C35_PD C35_PE C35_PF C36_PA C36_PB C36_PC C36_PD C36_PE C36_PF: library part CMP-0008973-2, "CAP, CERM, 0.1 uF, 250 V, +/- 10%, X7R, 1206", Cap_Case=1206, Manufacturer=MuRata, Supplier Part Number 1=490-3542-1-ND, TempCo=X7R, Tolerance_%=10%, Value1=Unknown, Value2=250V, ValueDisplayed=0.1uF
C37_PA C37_PB C37_PC C37_PD C37_PE C37_PF C41_PA C41_PB C41_PC C41_PD C41_PE C41_PF C42_PA C42_PB C42_PC C42_PD C42_PE C42_PF: library part CMP-0006812-4, "CAP, CERM, 100 pF, 10 V, +/- 10%, X7R, 0603", Cap_Case=0603, Manufacturer=AVX, Supplier Part Number 1=0603ZC101KAT2A-ND, TempCo=X7R, Tolerance_%=10%, Value1=Unknown, Value2=10V, ValueDisplayed=100pF
C38_PA C38_PB C38_PC C38_PD C38_PE C38_PF C39_PA C39_PB C39_PC C39_PD C39_PE C39_PF C40_PA C40_PB C40_PC C40_PD C40_PE C40_PF: library part CMP-0009427-2, "CAP, CERM, 3.3 uF, 250 V, +/- 20%, X7T, AEC-Q200 Grade 1, 6x5x5mm", Cap_Case=2220, Manufacturer=TDK, Supplier Part Number 1=445-7108-1-ND, TempCo=X7T, Tolerance_%=20%, Value1=Unknown, Value2=250V, ValueDisplayed=3.3uF
C43_PA C43_PB C43_PC C43_PD C43_PE C43_PF: library part CMP-0007126-4, "CAP, CERM, 15 pF, 50 V, +/- 5%, C0G/NP0, AEC-Q200 Grade 1, 0603", Cap_Case=0603, Manufacturer=MuRata, Supplier Part Number 1=490-4957-1-ND, TempCo=C0G/NP0, Tolerance_%=5%, Value1=Unknown, Value2=50V, ValueDisplayed=15pF
C44_PA C44_PB C44_PC C44_PD C44_PE C44_PF: library part CMP-0076706-1, "CAP, CERM, 4.7 µF, 25 V,+/- 10%, X7R, AEC-Q200 Grade 1, 0805", Cap_Case=2x1.25x1.25mm, Manufacturer=TDK, Supplier Part Number 1=445-6967-1-ND, TempCo=X7R, Tolerance_%=10%, Value2=25V, ValueDisplayed=4.7µF
C46_PA C46_PB C46_PC C46_PD C46_PE C46_PF C51_PA C51_PB C51_PC C51_PD C51_PE C51_PF C52_PA C52_PB C52_PC C52_PD C52_PE C52_PF C55_PA C55_PB C55_PC C55_PD C55_PE C55_PF: library part CMP-0083705-1, "CAP, CERM, 1 µF, 50 V,+/- 10%, X7R, AEC-Q200 Grade 1, 0805", Cap_Case=0805, Manufacturer=AVX, Supplier Part Number 1=478-9557-1-ND, TempCo=X7R, Tolerance_%=10%, Value2=50V, ValueDisplayed=1µF
C47_PA C47_PB C47_PC C47_PD C47_PE C47_PF: library part CMP-0007097-4, "CAP, CERM, 0.47 uF, 50 V, +/- 10%, X7R, AEC-Q200 Grade 1, 0603", Cap_Case=0603, Manufacturer=TDK, Supplier Part Number 1=445-172475-1-ND, TempCo=X7R, Tolerance_%=10%, Value1=Unknown, Value2=50V, ValueDisplayed=0.47uF
C48_PA C48_PB C48_PC C48_PD C48_PE C48_PF C49_PA C49_PB C49_PC C49_PD C49_PE C49_PF: library part CMP-0080062-1, "CAP, CERM, 47 pF, 50 V,+/- 5%, C0G/NP0, AEC-Q200 Grade 0, 0603", Cap_Case=0603, Manufacturer=TDK, Supplier Part Number 1=445-12417-1-ND, TempCo=C0G/NP0, Tolerance_%=5%, Value2=50V, ValueDisplayed=47pF
C54_PA C54_PB C54_PC C54_PD C54_PE C54_PF: library part CMP-0007163-4, "CAP, CERM, 1500 pF, 25 V, +/- 5%, C0G/NP0, 0603", Cap_Case=0603, Manufacturer=MuRata, Supplier Part Number 1=GRM1885C1E152JA01D-ND, TempCo=C0G/NP0, Tolerance_%=5%, Value1=Unknown, Value2=25V, ValueDisplayed=1500pF
D1 D2 D3 D4 D5 D6 D7 D16: library part CMP-0028644-3, "Diode, Schottky, 70 V, 0.07 A, SOD-523", Manufacturer=Nexperia, Value1=0.07A, Value2=0.41V
D8_PA D8_PB D8_PC D8_PD D8_PE D8_PF D9_PA D9_PB D9_PC D9_PD D9_PE D9_PF: library part CMP-0028981-2, "Diode, Schottky, 200 V, 1 A, SMA", Manufacturer="Micro Commercial Components", Value1=1A, Value2=0.92V
D10 D12 D13 D14 D17: library part CMP-0002953-3, "LED, Green, SMD", Color=Green, Manufacturer=Kingbright, Power_TotalModule=75mW, Value1=0.075W, Value2=2.65V
D11_PA D11_PB D11_PC D11_PD D11_PE D11_PF: library part CMP-0005773-4, "Diode, Zener, 12 V, 500 mW, AEC-Q101, SOD-123", Manufacturer=Vishay-Semiconductor, Power_W=500mW, Value1=0.5W
D15_PA D15_PB D15_PC D15_PD D15_PE D15_PF: library part CMP-0028517-2, "Diode, Schottky, 200 V, 1 A, PowerDI123", Manufacturer="Diodes Inc.", Value1=1A, Value2=0.85V
FID1 FID2 FID3: library part CMP-0077181-1, "Fiducial mark.  There is nothing to buy or mount.", Manufacturer=N/A
H1 H2 H3 H4: library part CMP-0003617-1, "Machine Screw, Round, #4-40 x 1/4, Nylon, Philips panhead", Manufacturer="B&F Fastener Supply", Supplier Part Number 1=H542-ND
J1 J2 J3 J4 J5 J6 J7 J8: library part CMP-0075441-1, "Connector, Receptacle, 100mil, 10x1, Gold plated, TH", Manufacturer=Samtec
J9 J10: library part CMP-0075292-1, "Terminal Block, 3x1, 5.08 mm, Tin, TH", Color=Blue, Current_A=15A, Manufacturer="On-Shore Technology", Supplier Part Number 1=ED2610-ND, Voltage_V=300V
J11 J13: library part CMP-0075044-1, "Terminal Block, 2-pole, 200mil, TH", Manufacturer="On-Shore Technology", Supplier Part Number 1=ED2609-ND
J12 J17_PA J17_PB J17_PC J17_PD J17_PE J17_PF: library part CMP-0075407-2, "Header, 100mil, 3x1, Gold, TH", Color=Black, Current_A=6.3A, Manufacturer=Samtec, Supplier Part Number 1=SAM1029-03-ND, Voltage_V=550V
J14: library part CMP-0054567-1, "Header, 100mil, 6x1, Tin, TH", Manufacturer="Sullins Connector Solutions", Supplier Part Number 1=S1012E-06-ND
J15: library part CMP-0002337-1, "Header, 100mil, 2x1, Tin, TH", Color=Black, Current_A=3A, Manufacturer="Sullins Connector Solutions", Supplier Part Number 1=S1012E-02-ND, Voltage_V=1.8kV
LBL1: library part THT-14-423-10, "Thermal Transfer Printable Labels, 0.650\" W x 0.200\" H - 10,000 per roll", Alternate Manufacturer=-, Manufacturer=Brady, Supplier Part Number 1=2065596
Logo1: library part CMP-0074838-1, "Texas Instrument Corporate Signature"
Logo2: library part CMP-0074844-2, Manufacturer="Texas Instruments"
Logo3: library part CMP-0074769-4, Manufacturer="Texas Instruments"
Logo6: library part CMP-0074847-1, "FCC_disclaimer"
Logo7: library part CMP-0074839-1
Q1_PA Q1_PB Q1_PC Q1_PD Q1_PE Q1_PF Q2: library part CMP-0000409-2, "Transistor, NPN, 40 V, 0.2 A, 3-UFDFN", Manufacturer="Diodes Inc.", Supplier Part Number 1=MMBT3904LP-7BDICT-ND, Value1="0.2 A", Value2=400
R1 R2 R29 R30 R75_PA R75_PB R75_PC R75_PD R75_PE R75_PF R77_PA R77_PB R77_PC R77_PD R77_PE R77_PF R79_PA R79_PB R79_PC R79_PD R79_PE R79_PF R84_PA R84_PB R84_PC R84_PD R84_PE R84_PF R87_PA R87_PB R87_PC R87_PD R87_PE R87_PF R89_PA R89_PB R89_PC R89_PD R89_PE R89_PF R90_PA R90_PB R90_PC R90_PD R90_PE R90_PF R94_PA R94_PB R94_PC R94_PD R94_PE R94_PF R100 R101 R103 R104 R105 R106 R107 R108 R115 R116 R117 R118: library part CMP-0025885-5, "RES, 0, 5%, 0.1 W, 0603", Manufacturer=Yageo, Power_W=100mW, Supplier Part Number 1=311-0.0GRCT-ND, TempCo="200 ppm/C", Tolerance_%=5%, Value2=0.1W, Value_Code=0000, ValueDisplayed=0
R3 R4 R5 R6 R7 R10 R11 R12 R14 R31 R32 R33 R34 R37 R38 R72 R109 R113: library part CMP-0022908-4, "RES, 20.0, 1%, 0.1 W, 0603", Manufacturer=Yageo, Power_W=100mW, Supplier Part Number 1=311-20.0HRCT-ND, TempCo="100 ppm/C", Tolerance_%=1%, Value2=0.1W, Value_Code=20R0, ValueDisplayed=20.0
R8 R9 R13 R15 R16 R17 R18 R19 R20 R21 R22 R23 R24 R25 R26 R27 R28 R35 R36 R39 R40 R41 R42 R43 R44 R45 R46 R47 R48 R49 R50 R51 R52 R53 R55 R65 R81_PA R81_PB R81_PC R81_PD R81_PE R81_PF R93_ R93_ R93_ R93_ R93_ R93_ R95_PA R95_PB R95_PC R95_PD R95_PE R95_PF R96 R97 R98 R99: library part CMP-0022746-5, "RES, 10.0 k, 1%, 0.1 W, 0603", Manufacturer=Yageo, Power_W=100mW, Supplier Part Number 1=311-10.0KHRCT-ND, TempCo="100 ppm/C", Tolerance_%=1%, Value2=0.1W, Value_Code=10k0, ValueDisplayed=10.0k
R54 R64: library part CMP-0022447-4, "RES, 49.9 k, 1%, 0.1 W, AEC-Q200 Grade 0, 0603", Manufacturer=Vishay-Dale, Power_W=100mW, Supplier Part Number 1=541-49.9KHCT-ND, TempCo="100 ppm/C", Tolerance_%=1%, Value2=0.1W, Value_Code=49k9, ValueDisplayed=49.9k
R56 R88_PA R88_PB R88_PC R88_PD R88_PE R88_PF: library part CMP-0022735-5, "RES, 100 k, 1%, 0.1 W, 0603", Manufacturer=Yageo, Power_W=100mW, Supplier Part Number 1=311-100KHRCT-ND, TempCo="100 ppm/C", Tolerance_%=1%, Value2=0.1W, Value_Code=100k
R57 R92_PA R92_PB R92_PC R92_PD R92_PE R92_PF R112: library part CMP-0023146-5, "RES, 4.22 k, 1%, 0.1 W, 0603", Manufacturer=Yageo, Power_W=100mW, Supplier Part Number 1=311-4.22KHRCT-ND, TempCo="100 ppm/C", Tolerance_%=1%, Value2=0.1W, Value_Code=4k22, ValueDisplayed=4.22k
R58 R66: library part CMP-0022410-4, "RES, 40.2 k, 1%, 0.1 W, AEC-Q200 Grade 0, 0603", Manufacturer=Vishay-Dale, Power_W=100mW, Supplier Part Number 1=541-40.2KHCT-ND, TempCo="100 ppm/C", Tolerance_%=1%, Value2=0.1W, Value_Code=40k2, ValueDisplayed=40.2k
R59 R67: library part CMP-0022448-4, "RES, 49.9, 1%, 0.1 W, AEC-Q200 Grade 0, 0603", Manufacturer=Vishay-Dale, Power_W=100mW, Supplier Part Number 1=541-49.9HCT-ND, TempCo="100 ppm/C", Tolerance_%=1%, Value2=0.1W, Value_Code=49R9, ValueDisplayed=49.9
R60 R68: library part CMP-0022424-4, "RES, 442 k, 1%, 0.1 W, AEC-Q200 Grade 0, 0603", Manufacturer=Vishay-Dale, Power_W=100mW, Supplier Part Number 1=541-442KHCT-ND, TempCo="100 ppm/C", Tolerance_%=1%, Value2=0.1W, Value_Code=442k
R61 R102 R110: library part CMP-0022043-4, "RES, 13.3 k, 1%, 0.1 W, AEC-Q200 Grade 0, 0603", Manufacturer=Vishay-Dale, Power_W=100mW, Supplier Part Number 1=541-13.3KHCT-ND, TempCo="100 ppm/C", Tolerance_%=1%, Value2=0.1W, Value_Code=13k3, ValueDisplayed=13.3k
R62 R70: library part CMP-0022204-4, "RES, 20.0 k, 1%, 0.1 W, AEC-Q200 Grade 0, 0603", Manufacturer=Vishay-Dale, Power_W=100mW, Supplier Part Number 1=541-20.0KHCT-ND, TempCo="100 ppm/C", Tolerance_%=1%, Value2=0.1W, Value_Code=20k0, ValueDisplayed=20.0k
R63: library part CMP-0022134-4, "RES, 1.82 k, 1%, 0.1 W, AEC-Q200 Grade 0, 0603", Manufacturer=Vishay-Dale, Power_W=100mW, Supplier Part Number 1=541-1.82KHCT-ND, TempCo="100 ppm/C", Tolerance_%=1%, Value2=0.1W, Value_Code=1k82, ValueDisplayed=1.82k
R69: library part CMP-0022454-4, "RES, 4.53 k, 1%, 0.1 W, AEC-Q200 Grade 0, 0603", Manufacturer=Vishay-Dale, Power_W=100mW, Supplier Part Number 1=541-4.53KHCT-ND, TempCo="100 ppm/C", Tolerance_%=1%, Value2=0.1W, Value_Code=4k53, ValueDisplayed=4.53k
R71: library part CMP-0022109-5, "RES, 1.00 k, 1%, 0.1 W, AEC-Q200 Grade 0, 0603", Manufacturer=Vishay-Dale, Power_W=100mW, Supplier Part Number 1=541-1.00KHCT-ND, TempCo="100 ppm/C", Tolerance_%=1%, Value2=0.1W, Value_Code=1k00, ValueDisplayed=1.00k
R73: library part CMP-0022512-4, "RES, 5.49 k, 1%, 0.1 W, AEC-Q200 Grade 0, 0603", Manufacturer=Vishay-Dale, Power_W=100mW, Supplier Part Number 1=541-5.49KHCT-ND, TempCo="100 ppm/C", Tolerance_%=1%, Value2=0.1W, Value_Code=5k49, ValueDisplayed=5.49k
R74: library part CMP-0022636-4, "RES, 8.45 k, 1%, 0.1 W, AEC-Q200 Grade 0, 0603", Manufacturer=Vishay-Dale, Power_W=100mW, Supplier Part Number 1=541-8.45KHCT-ND, TempCo="100 ppm/C", Tolerance_%=1%, Value2=0.1W, Value_Code=8k45, ValueDisplayed=8.45k
R76_PA R76_PB R76_PC R76_PD R76_PE R76_PF R85_PA R85_PB R85_PC R85_PD R85_PE R85_PF: library part CMP-0015751-2, "RES, 0.005, 1%, 3 W, AEC-Q200 Grade 0, 2512", Manufacturer=Bourns, Power_W=3W, Supplier Part Number 1=CRE2512-FZ-R005E-3CT-ND, TempCo="75 ppm/C", Tolerance_%=1%, Value_Code=5L000, ValueDisplayed=0.005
